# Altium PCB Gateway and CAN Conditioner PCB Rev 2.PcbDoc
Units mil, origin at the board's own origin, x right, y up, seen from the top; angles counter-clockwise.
Board outline 4000 x 3250 mil, 2 copper layers (Top Layer, Bottom Layer); 40 components, 47 nets, 193 pads, 19 vias.
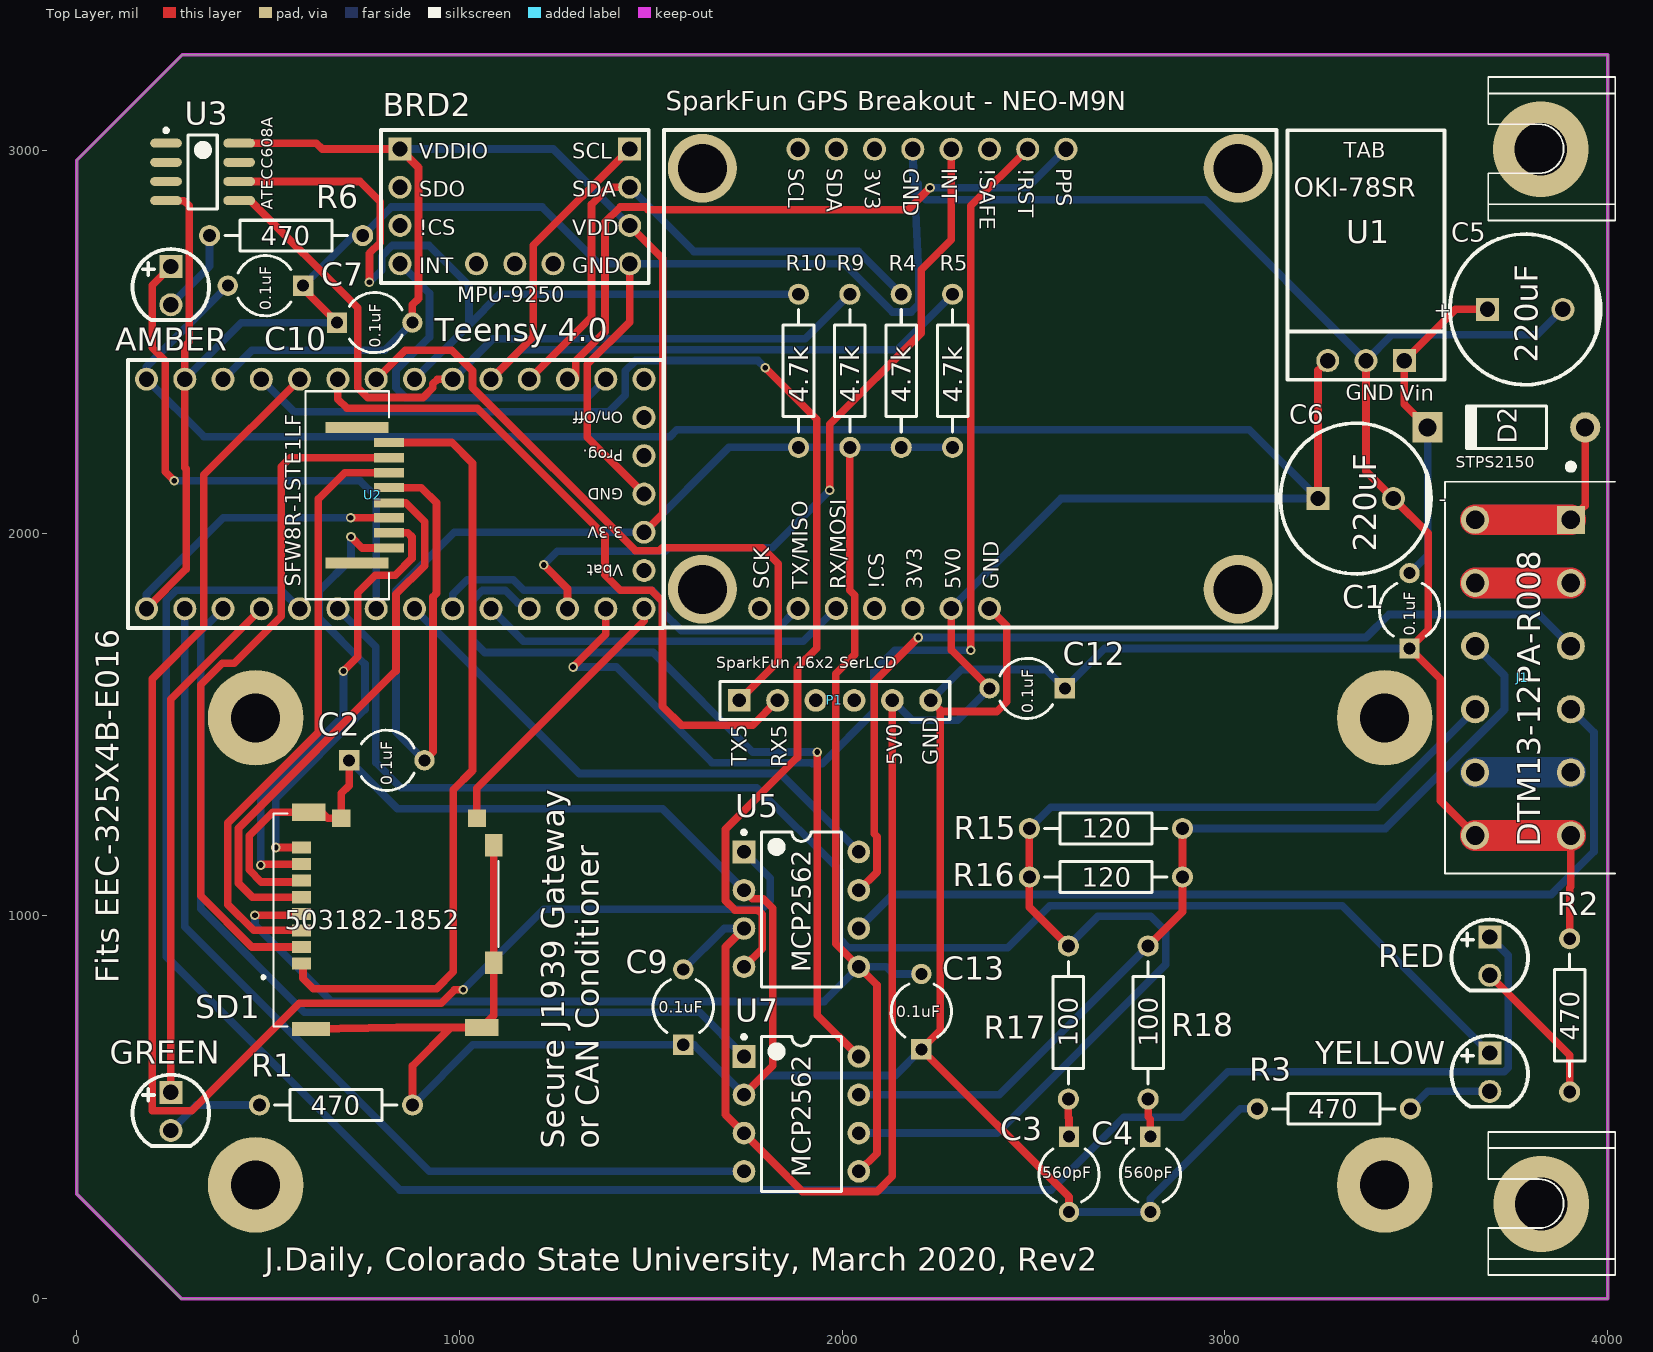
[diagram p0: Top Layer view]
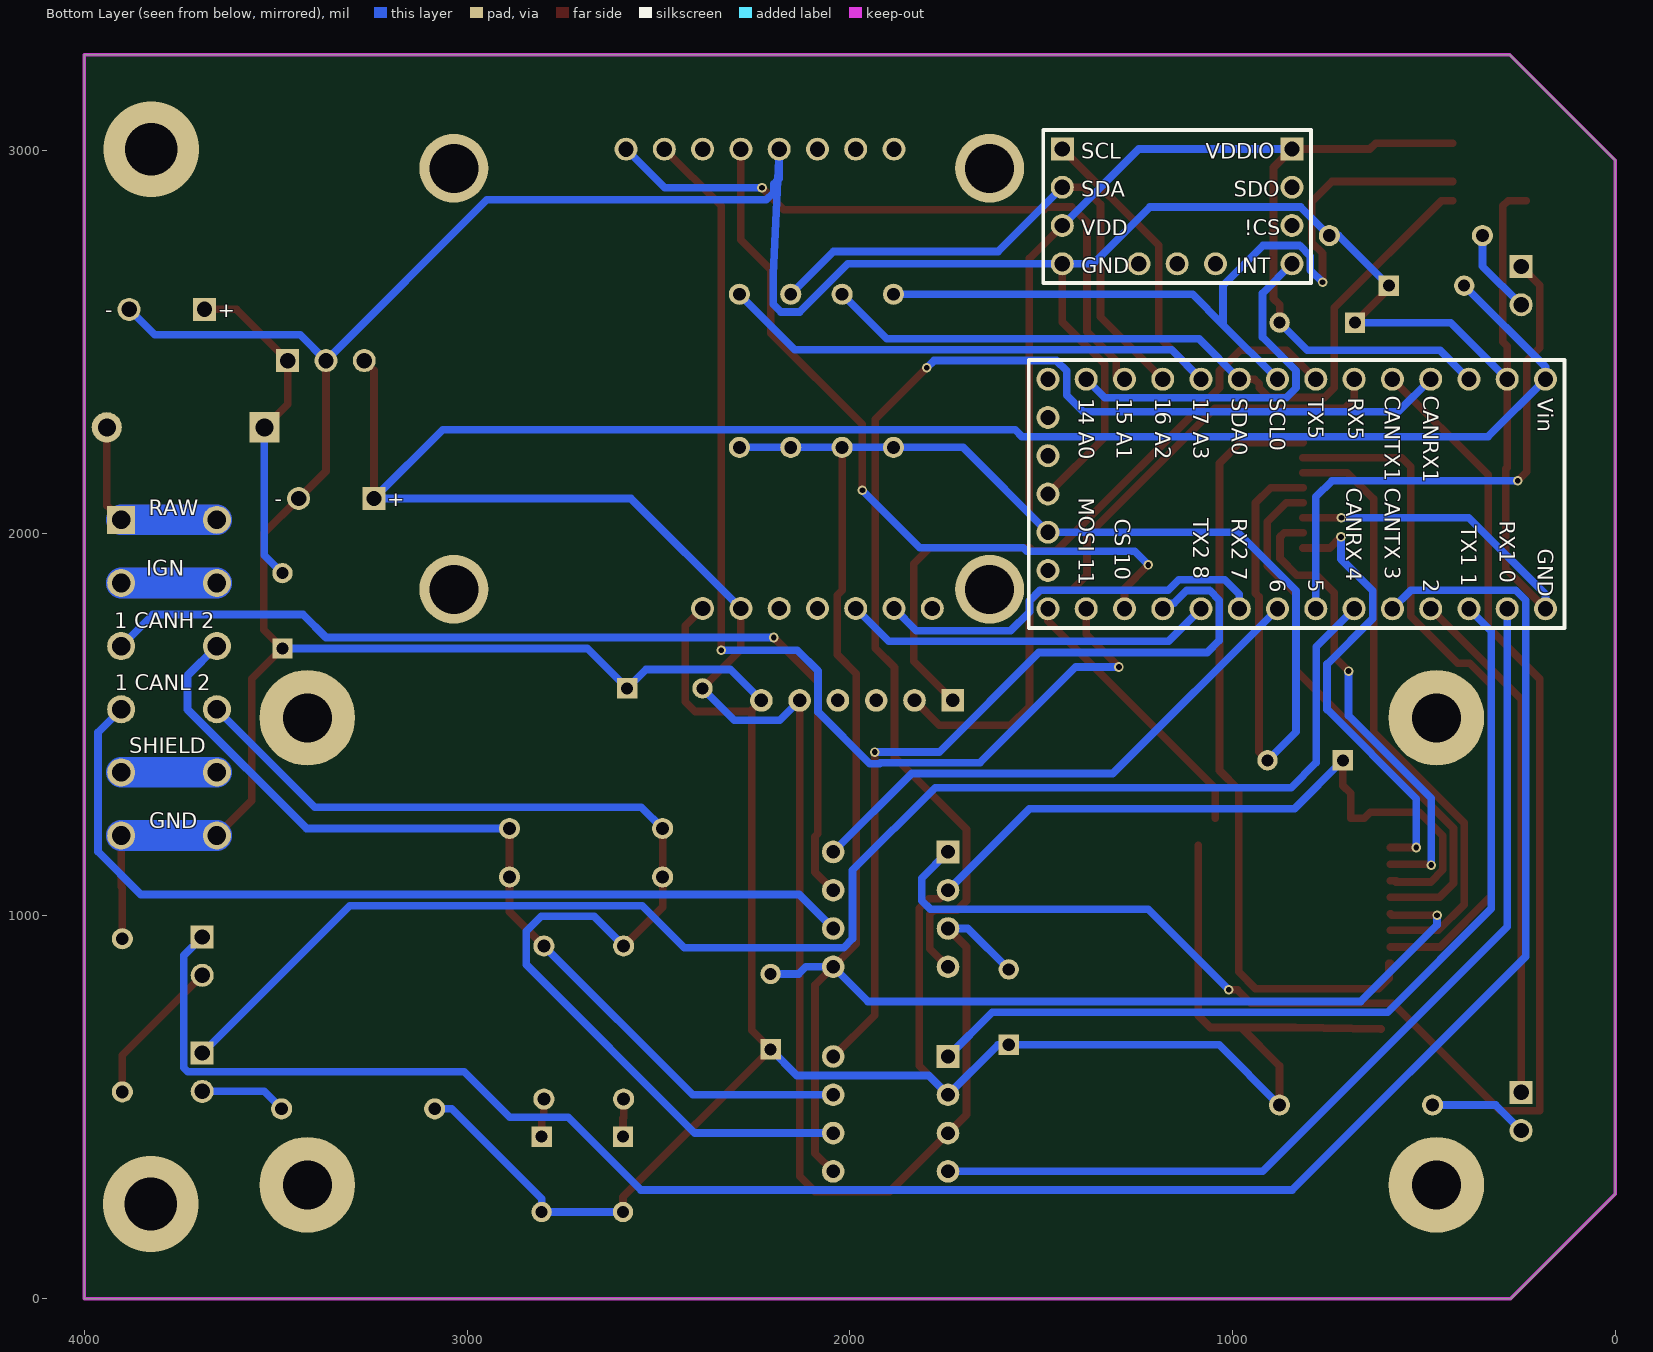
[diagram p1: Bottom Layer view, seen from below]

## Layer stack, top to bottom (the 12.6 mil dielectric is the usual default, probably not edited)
Top Solder: solder mask 0.4, Solder Resist, Dk 3.5
Top Layer: signal copper 1.4
Dielectric 1: dielectric 12.6, FR-4, Dk 4.8
Bottom Layer: signal copper 1.4
Bottom Solder: solder mask 0.4, Solder Resist, Dk 3.5

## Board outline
0,273.11 273.11,0 4000,0 4000,3250 275.59,3250 0,2974.41

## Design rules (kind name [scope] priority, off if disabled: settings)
Clearance [All] p1: gap=8 ignorepadtopadclearanceinfootprint=FALSE
PolygonConnect [All] p1: connectstyle=Relief reliefconductorwidth=10 reliefentries=4 polygonreliefangle="90 Angle" airgapwidth=10
RoutingVias [All] p1: holewidth=15 width=25 viastyle="Through Hole" minholewidth=10 minwidth=20 maxholewidth=30 maxwidth=50
SolderMaskExpansion [All] p1: expansion=4
Width [All] p1: maxlimit=39.37 minlimit=10 preferedwidth=20
30 further rules are at their usual default settings.

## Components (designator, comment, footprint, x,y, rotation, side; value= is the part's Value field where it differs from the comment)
AMBER "Amber" "5mm Rad LED" 247.05,2644.68 r0 top (schematic designator D5)
BRD2 "Sparkfun MPU-9250" "MPU9250 Breakout" 844.68,2703.74 r0 top
C1 "0.1uF" CAPR5-4X5 3482.28,1797.24 r90 top
C2 "0.1uF" CAPR5-4X5 810.04,1406.5 r0 top
C3 "560pF" CAPR5-4X5 2592.52,324.8 r270 top
C4 "560pF" CAPR5-4X5 2805.12,324.8 r270 top
C5 "220uF" "Elec. Cap 5 x 10mm" 3686.02,2584.65 r0 top
C6 "220uF" "Elec. Cap 5 x 10mm" 3243.11,2090.55 r0 top
C7 "0.1uF" CAPR5-4X5 493.11,2646.65 r180 top
C9 "0.1uF" CAPR5-4X5 1584.65,761.81 r90 top
C10 "0.1uF" CAPR5-4X5 778.54,2550.2 r0 top
C12 "0.1uF" CAPR5-4X5 2483.27,1594.49 r180 top
C13 "0.1uF" CAPR5-4X5 2206.69,750 r90 top
D2 "STPS2150" DO-204AL 3735.24,2276.57 r180 top
GREEN "Green" "5mm Rad LED" 247.05,487.2 r0 top (schematic designator D1)
J1 "DTM13-12PA-R008" TE_DTM13-12PA-R008 3826.38,1622.44 r90 top locked
P1 "Header 6" HDR1X6 1730.91,1562.99 r0 top
R1 "470" AXIAL-0.4 677.36,505.91 r0 top
R2 "470" AXIAL-0.4 3900.59,740.35 r90 top
R3 "470" AXIAL-0.4 3284.45,496.06 r180 top
R4 "4.7k" AXIAL-0.4 2154.2,2424.21 r90 top
R5 "4.7k" AXIAL-0.4 2288.39,2424.21 r90 top
R6 "470" AXIAL-0.4 547.05,2777.56 r0 top
R9 "4.7k" AXIAL-0.4 2020.01,2424.21 r90 top
R10 "4.7k" AXIAL-0.4 1885.83,2424.21 r90 top
R15 "120" AXIAL-0.4 2688.98,1228.35 r0 top
R16 "120" AXIAL-0.4 2688.98,1101.71 r0 top
R17 "100" AXIAL-0.4 2590.88,721.46 r90 top
R18 "100" AXIAL-0.4 2799.21,721.46 r90 top
RED "Red" "5mm Rad LED" 3692.91,892.72 r0 top (schematic designator D3)
SD1 "503182-1852" MOLEX_503182-1852 837.6,989.76 r90 top
"SparkFun 16x2 SerLCD" "Comment" LCD14072 467.32,297.24 r0 top locked
"SparkFun GPS Breakout - NEO-M9N" "GPS NEO M9N" "GPS NEO M9N" 3034.45,2953.35 r180 top locked (schematic designator BRD1)
"Teensy 4.0" "Teensy 4.0" "Teensy 4.0" 1482.28,1802.36 r90 top (schematic designator "Teensy 1")
U1 "OKI-78SR" OKI-78SR 3268.5,2450.79 r0 top
U2 "SFW8R-1STE1LF" FCI_SFW8R-1STE1LF 923.95,2099.1 r90 top
U3 "ATECC608A" SOIC-8 328.74,2943.9 r0 top
U5 "MCP2562" DIP-8 1893.31,1017.13 r0 top
U7 "MCP2562" DIP-8 1893.31,482.68 r0 top
YELLOW "Yellow" "5mm Rad LED" 3692.91,589.57 r0 top (schematic designator D4)

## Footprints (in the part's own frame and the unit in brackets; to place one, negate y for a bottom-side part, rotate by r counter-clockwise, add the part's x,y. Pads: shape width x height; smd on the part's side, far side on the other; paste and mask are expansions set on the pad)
"5mm Rad LED" [mil]
  rect 60x60 hole 40: 1(-1.11,52.05)
  round 60 hole 40: 2(-1.11,-47.95)
  silkscreen extent -101,-88 99,98
AXIAL-0.4 [mm] "Axial Device, Thru-Hole; 2 Leads; 0.4 in Pin Spacing"
  round 1.4 hole 0.85: 1(-5.08,0) 2(5.08,0)
  silkscreen extent -4.06,-1.02 4.06,1.02
CAPR5-4X5 [mm] "Capacitor; 2 Leads"
  rect 1.35x1.35 hole 0.8: 1(-2.5,0)
  round 1.35 hole 0.8: 2(2.5,0)
  silkscreen extent -1.69,-2 1.82,2
DIP-8 [mm] "DIP; 8 Leads; Row Spacing 7.62 mm; Pitch 2.54 mm"
  rect 1.5x1.5 hole 0.9: 1(-3.81,3.81)
  round 1.5 hole 0.9: 2(-3.81,1.27) 3(-3.81,-1.27) 4(-3.81,-3.81) 5(3.81,-3.81) 6(3.81,-1.27) 7(3.81,1.27) 8(3.81,3.81)
  silkscreen extent -3.93,-5.15 2.65,5.23, body extent -3.6,-5.15 3.6,5.15, height 5.08
DO-204AL [mm] "Diode, Axial; Body 5.2 x 2.7 mm (LxDia. max), Lead Dia. 0.86 mm (max)"
  round 2 hole 1.2: 1(-5.23,0)
  rect 2x2 hole 1.2: 2(5.23,0)
  silkscreen extent -2.65,-1.4 2.75,1.4
"Elec. Cap 5 x 10mm" [mil] "2 lead polarized Radial Capacitor with 5 mm lead spacing and 10 mm diameter can"
  rect 60x60 hole 40: 1(0,0)
  round 60 hole 40: 2(196.85,0)
  silkscreen extent -98,-197 295,197
FCI_SFW8R-1STE1LF [mil]
  rect 24x79 smd: 1(138,108) 2(98,108) 3(59,108) 4(20,108) 5(-20,108) 6(-59,108) 7(-98,108) 8(-138,108)
  rect 28x165 smd: 9(-177,192) 10(177,192)
  silkscreen extent -272,108 272,326
"GPS NEO M9N" [mil] "Sparkfun Breakout"
  round 180 hole 128: 0(0,1100) 0(0,0) 0(1400,1100) 0(1400,0)
  round 60 hole 40: 1(450,-50) 2(550,-50) 3(650,-50) 4(750,-50) 5(850,-50) 6(950,-50) 7(1050,-50) 8(1150,-50) 9(1250,1150) 10(1150,1150) 11(1050,1150) 12(950,1150) 13(850,1150) 14(750,1150) 15(650,1150)
  silkscreen extent -100,-100 1500,1200
HDR1X6 [mm] "Connector; Header; 6 Position"
  rect 1.5x1.5 hole 0.9: 1(0,0)
  round 1.5 hole 0.9: 2(2.54,0) 3(5.08,0) 4(7.62,0) 5(10.16,0) 6(12.7,0)
  silkscreen extent -1.27,-1.27 13.97,1.27
LCD14072 [mil] "SparkFun 16x2 SerLCD dimensions front"
  round 250 hole 128: 0(0,0) 0(0,1220.47) 0(2950,0) 0(2950,1220.47)
MOLEX_503182-1852 [mm]
  rect 0.8x1.24 smd: 1(-2.9,6.355) 2(-1.8,6.355) 3(-0.7,6.355) 4(0.4,6.355) 5(1.5,6.355) 6(2.6,6.355) 7(3.7,6.355) 8(4.8,6.355)
  rect 1.16x1.2 smd: DT(6.74,-5.275)
  rect 0.95x2.5 smd: P1(-7.245,5.725)
  rect 1.15x2.2 smd: P2(7.145,5.875) P3(-7.145,-5.605)
  rect 1.5x1.15 smd: P4(-2.84,-6.4) P5(4.94,-6.4)
  rect 1.16x1.25 smd: SW(6.74,3.725)
  silkscreen extent -7.07,-6.72 7.07,8.99
"MPU9250 Breakout" [mil] "SparkFun IMU Breakout - MPU-9250"
  rect 60x60 hole 40: 1(0,300) 8(600,300)
  round 60 hole 40: 2(0,200) 3(0,100) 4(0,0) 5(600,0) 6(600,100) 7(600,200) 9(200,0) 10(300,0) 11(400,0)
  silkscreen extent -50,-50 650,350
OKI-78SR [mil] "Horizontal Mount SIP DC/DC Converter"
  rect 60x60 hole 40: 1(200,0)
  round 60 hole 40: 2(100,0) 3(0,0)
  silkscreen extent -105,-50 305,602
SOIC-8 [mm]
  oval 2.1x0.6 smd: 1(-2.425,1.905) 2(-2.425,0.635) 3(-2.425,-0.635) 4(-2.425,-1.905) 5(2.425,-1.905) 6(2.425,-0.635) 7(2.425,0.635) 8(2.425,1.905)
  silkscreen extent -2.55,-2.45 0.97,2.88
TE_DTM13-12PA-R008 [mm]
  rect 1.86x1.86 hole 1.24: 1(10.475,-1.96)
  round 1.86 hole 1.24: 2(6.285,-1.96) 3(2.095,-1.96) 4(-2.095,-1.96) 5(-6.285,-1.96) 6(-10.475,-1.96) 7(-10.475,4.39) 8(-6.285,4.39) 9(-2.095,4.39) 10(2.095,4.39) 11(6.285,4.39) 12(10.475,4.39)
  silkscreen extent -39.65,-4.91 39.85,6.39
"Teensy 4.0" [mil] "32 bit Arduino Compatible Microcontroller www.pjrc.com/teensy"
  round 60 hole 40: 0(0,1200) 1(0,1100) 2(0,1000) 3(0,900) 3V3a(600,1100) 3V3b(200,0) 4(0,800) 5(0,700) 6(0,600) 7(0,500) 8(0,400) 9(0,300) 10(0,200) 11(0,100) 12(0,0) 13(600,0) 14(600,100) 15(600,200) 16(600,300) 17(600,400) 18(600,500) 19(600,600) 20(600,700) 21(600,800) 22(600,900) 23(600,1000) G1(0,1300) G2(600,1200) G3(300,0) On(500,0) P(400,0) VBat(100,0) Vin(600,1300)
  silkscreen extent -50,-50 650,1348

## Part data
AMBER: library part "LED - SMD", "Amber 588nm LED Indication - Discrete 2.1V Radial", Manufacturer="Lite-On Inc.", PartNumber=LTL-4273, Supplier Part Number 1=160-1966-ND
BRD2: library part "MPU-9350 Breakout"
C1 C2 C7 C9 C10 C12 C13: library part Cap, "0.1µF ±10% 50V Ceramic Capacitor X7R Radial", Manufacturer="TDK Corporation", PartNumber=FA28X7R1H104KNU00, Supplier Part Number 1=445-175529-ND
C3 C4: library part Cap, "560pF ±5% 100V Ceramic Capacitor C0G, NP0 Radial", Manufacturer="TDK Corporation", PartNumber=FA28C0G2A561JNU00, Supplier Part Number 1=445-175528-ND
C5 C6: library part "Electrolytic Cap", "220µF 50V Aluminum Electrolytic Capacitors Radial, Can 175 mOhm @ 10kHz 5000 Hrs @ 105°C", Manufacturer="EPCOS (TDK)", PartNumber=B41858C6227M000, Supplier Part Number 1=495-6000-ND
D2: library part "Diode 1N4003", "Diode Schottky 150V 2A Through Hole DO-15", Manufacturer=STMicroelectronics, Supplier Part Number 1=497-3213-1-ND
GREEN: library part "LED - SMD", "Green 569nm LED Indication - Discrete 2.1V Radial", Manufacturer="Lite-On Inc.", PartNumber=LTL-4233, Supplier Part Number 1=160-1130-ND
J1: "DTM Series, 4.19mm Pitch 12 Way 2 Row Right Angle PCB Header, Solder Termination", Package=None
P1: "Header, 6-Pin"
R1 R2 R3 R6: library part "Chip Resistor", "330 Ohms ±1% 0.1W, 1/10W Chip Resistor 0603 (1608 Metric) Automotive AEC-Q200, High Voltage Thick Film", Manufacturer="Stackpole Electronics Inc", PartNumber=CF14JT470R, Supplier Part Number 1=CF14JT470RCT-ND
R4 R5 R9 R10: library part "Chip Resistor", "4.7 kOhms ±5% 0.25W, 1/4W Through Hole Resistor Axial Flame Retardant Coating, Safety Carbon Film", Manufacturer="Stackpole Electronics Inc", PartNumber=CF14JT4K70, Supplier Part Number 1=CF14JT4K70CT-ND
R15 R16: library part "Chip Resistor", "120 Ohms ±5% 0.25W, 1/4W Through Hole Resistor Axial Flame Retardant Coating, Safety Carbon Film", Manufacturer="Stackpole Electronics Inc", PartNumber=CF14JT120RCT-ND
R17 R18: library part "Chip Resistor", "100 Ohms ±5% 0.25W, 1/4W Through Hole Resistor Axial Flame Retardant Coating, Safety Carbon Film", Manufacturer="Stackpole Electronics Inc", PartNumber=CF14JT100R, Supplier Part Number 1=CF14JT100RCT-ND
RED: library part "LED - SMD", "Red 623nm LED Indication - Discrete 2V Radial", Manufacturer="Lite-On Inc.", PartNumber=LTL-4223, Supplier Part Number 1=160-1127-ND
SD1: "MICRO SD NORMAL ULTRALOWPRO8CKTE", Manufacturer=Molex, PartNumber=5031821852, Supplier Part Number 1=WM12834CT-ND
"Teensy 4.0": library part Teensy_4.0, "32 Bit Arduino-Compatible iMX Microcontroller", Manufacturer=PRJC, Supplier Part Number 1=1568-DEV-15583-ND
U1: library part 7805, "5V DC/DC Converter (7805 replacement)", Manufacturer="Murata Power Solutions Inc.", PartNumber=OKI-78SR-5/1.5-W36H-C, Supplier Part Number 1=811-2692-ND
U2: "8 Position FFC, FPC Connector Contacts, Bottom 0.039 _1.00mm_ Surface Mount, Right Angle", Package=None
U3: library part ATECC508A, "Authentication Chip IC Networking and Communications 8-SOIC", Manufacturer="Microchip Technology", PartNumber=ATECC608A-SSHDA-T, Supplier Part Number 1=ATECC608A-SSHDA-TCT-ND
U5 U7: library part MCP2558FD, "Microchip CAN FD Transceiver with Silent Mode", Manufacturer=Microchip, PartNumber=MCP2562-E/P, Supplier Part Number 1=MCP2562-E/P-ND
YELLOW: library part "LED - SMD", "Yellow 588nm LED Indication - Discrete 2.1V Radial", Manufacturer="Lite-On Inc.", PartNumber=LTL-4253, Supplier Part Number 1=160-1133-ND

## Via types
v1: diameter 25, hole 15, Top Layer to Bottom Layer, 17 vias
v2: diameter 250, hole 137.8, Top Layer to Bottom Layer, 2 vias

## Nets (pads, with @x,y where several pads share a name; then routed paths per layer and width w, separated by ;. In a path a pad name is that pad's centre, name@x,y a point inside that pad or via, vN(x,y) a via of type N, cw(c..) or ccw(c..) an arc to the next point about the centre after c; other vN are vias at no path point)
3V3: "Teensy 4.0.3V3a" "Teensy 4.0.3V3b" BRD2.1 BRD2.6 C2.2 C10.2 C13.2 R4.1 R5.1 R9.1 R10.1 SD1.4 U2.4 U3.8 U5.5 U7.5 | length 9913.2
  Top Layer w20: U3.8 626,3018.9 641.16,3003.74 BRD2.1 893,2955.43 893,2613 876.97,2596.97 C10.2 ; v1(465.55,1001.97) 583.86,1001.97 SD1.4 ; U2.4 900,2119.09 940,2079.09 940,1843 931,1834 931,1429.03 C2.2 ; BRD2.6 1531,2717.43 1531,2051.08 1482.28,2002.36 ; R9.1 2020.01,1851 2033,1838.01 2033,1683 1983,1633 1983,927.43 U5.5 2091,819.43 2091,380.37 U7.5
  Bottom Layer w20: 382.28,2402.36 457.92,2478 804.77,2478 C10.2 ; v1(465.55,1001.97) 465.55,976.4 665.37,776.59 1952.77,776.59 U5.5 2115,867.13 2133.7,848.42 C13.2 ; BRD2.1 1244.69,3003.74 BRD2.6 ; C2.2 834,1480.96 834,1850 986.36,2002.36 1482.28,2002.36 1704.14,2224.21 R10.1 R9.1 R4.1 R5.1
5V0: "SparkFun GPS Breakout - NEO-M9N.14" "Teensy 4.0.Vin" C6.1 C7.2 C9.2 C12.2 P1.5 U1.3 U5.3 U7.3 | length 8033.9
  Top Layer w20: U5.3 1695,918.82 1695,480.99 U7.3 1895.99,280 2091,280 2130.91,319.91 P1.5 ; 2284.45,1803.35 2284.45,1694.88 C12.2 ; C6.1 3243.11,2425.39 U1.3
  Bottom Layer w20: C7.2 182.28,2434.25 182.28,2402.36 332.65,2252 1550,2252 1568,2270 3063.66,2270 C6.1 2571.65,2090.55 2284.45,1803.35 ; C9.2 1691.54,967.13 U5.3 ; P1.5 2182.9,1511 2301.35,1511 C12.2
12V0: C1.2 C5.1 D2.2 U1.1 | length 872.8
  Top Layer w20: D2.2 3468.5,2337.4 U1.1 3602.36,2584.65 C5.1
  Bottom Layer w20: C1.2 3529.33,1942.72 D2.2
CAN1H: J1.3 U5.7 | length 2494.7
  Top Layer w20: U5.7 2091,1114.82 2091,1207 2083.38,1214.62 2083.38,1611.92 v1(2198.82,1727.36)
  Bottom Layer w20: v1(2198.82,1727.36) 3368.36,1727.36 3428.4,1787.4 3821.06,1787.4 J1.3
CAN1L: J1.4 U5.6 | length 2400.9
  Bottom Layer w20: U5.6 2132.18,1056 3852,1056 3964,1168 3964,1479.5 J1.4
CAN1RX: "Teensy 4.0.23" U5.4 | length 3266.4
  Top Layer w20: U5.4 1790.84,914.65 1790.84,1004.16 1780,1015 1720,1015 1695,1040 1695,1226 1883,1414 1883,1649 1933,1699 1933,2298 v1(1799,2432)
  Bottom Layer w20: 482.28,2402.36 567.65,2317 1390,2317 1433,2360 1433,2424 1460,2451 1780,2451 v1(1799,2432)
CAN1TX: "Teensy 4.0.22" U5.1 | length 4068.9
  Top Layer w20: 582.28,2402.36 332,2152.08 332,1754 197,1619 197,491 300,491 581,772 952,772 987.09,807.09 v1(1009.84,807.09)
  Bottom Layer w20: v1(1009.84,807.09) 1219.76,1017 1789,1017 1812,1040 1812,1098.43 U5.1
CAN2H: J1.10 R15.2 R16.2 R18.2 U7.7 | length 2428.5
  Top Layer w20: R18.2 2888.98,1011.22 R16.2 R15.2
  Bottom Layer w20: U7.7 2410.43,532.68 R18.2 ; R15.2 3419.29,1228.35 3730.31,1539.37 3730.31,1628.15 J1.10
CAN2L: J1.9 R15.1 R16.1 R17.2 U7.6 | length 3016
  Top Layer w20: R15.1 R16.1 2488.98,1023.36 R17.2
  Bottom Layer w20: U7.6 2404.68,432.68 2845,873 2845,960 2806.24,998.76 2668.18,998.76 R17.2 ; R15.1 2544.63,1284 3397.58,1284 J1.9
CAN2RX: "Teensy 4.0.0" U7.4 | length 2556.4
  Bottom Layer w20: 282.28,1802.36 282.28,971.72 921.32,332.68 U7.4
CAN2TX: "Teensy 4.0.1" U7.1 | length 2386.6
  Bottom Layer w20: 382.28,1802.36 324,1744.08 324,1019.37 594.79,748.59 1627.4,748.59 U7.1
DAT0: SD1.7 U2.7 | length 1223.2
  Top Layer w20: v1(481.11,1132.87) 483.67,1135.43 SD1.7 ; v1(696.85,1639.76) 734,1676.91 734,1844 780,1890 832,1890 876,1934 876,1990 864.91,2001.09 U2.7
  Bottom Layer w20: v1(481.11,1132.87) 481.11,1307.11 696.85,1522.85 v1(696.85,1639.76)
DAT1: SD1.8 U2.8 | length 1170.3
  Top Layer w20: v1(520,1178.74) SD1.8 ; v1(716.54,1990.16) 745.6,1961.09 U2.8
  Bottom Layer w20: v1(520,1178.74) 520,1306.4 753,1539.4 753,1658 634,1777 634,1850 716.54,1932.54 v1(716.54,1990.16)
DAT2: SD1.1 U2.1 | length 2054.8
  Top Layer w20: SD1.1 591,875.59 591,837 618,810 940,810 984,854 984,1330 1034,1380 1034,2183.09 980,2237.09 U2.1
DAT3: SD1.2 U2.2 | length 1836.5
  Top Layer w20: SD1.2 552.18,918.9 551.94,918.65 457.84,918.65 324,1052.49 324,1604 380,1660 411,1660 534,1783 534,2173 558.09,2197.09 U2.2
GND: "SparkFun GPS Breakout - NEO-M9N.5" "SparkFun GPS Breakout - NEO-M9N.15" "Teensy 4.0.G1" "Teensy 4.0.G2" "Teensy 4.0.G3" BRD2.5 C1.1 C2.1 C3.2 C4.2 C5.2 C6.2 C7.1 C9.1 C10.1 C12.1 C13.1 J1.6 J1.7 P1.6 R1.2 R2.2 R3.2 R6.2 SD1.6 SD1.P1 SD1.P2 SD1.P3 SD1.P4 SD1.P5 SD1.SW U1.2 U2.6 U3.4 U5.2 U7.2 | length 18492.1
  Top Layer w20: 182.28,1802.36 286.48,1906.56 286.48,2167.54 282.28,2171.74 282.28,2402.36 282.28,2488.28 294,2500 294,2854.9 280,2868.9 U3.4 ; SD1.6 572.99,1092.12 572.99,1088.5 482.35,1088.5 450.61,1120.24 450.61,1209.06 512.62,1271.06 SD1.P2 640,1271.06 655.95,1255.12 SD1.SW 690.94,1320 711.61,1340.67 C2.1 ; C7.1 591.54,2638.78 C10.1 ; SD1.P1 836.94,708.46 977.46,708.46 ; v1(715.55,2040.35) 815.68,2040.35 U2.6 ; R1.2 877.36,608.36 977.46,708.46 ; SD1.P5 SD1.P4 1089.57,739.76 SD1.P3 977.46,708.46 ; BRD2.5 1444.69,2551.69 1334,2441 1334,2250.65 1482.28,2102.36 ; U7.2 1818.84,608.21 1818.84,1020 1793.71,1045.13 1765.31,1045.13 U5.2 ; P1.6 2256,1537.9 ; 2384.45,1803.35 2430,1757.79 2430,1560 2404,1534 2259.9,1534 2256,1537.9 ; C3.2 2592.52,265.75 C13.1 2256,700.88 2256,1537.9 ; U1.2 3368.5,2162.01 C6.2 3531,1999.51 3531,1747.53 C1.1 3562,1619.1 3562,1301.58 J1.7 ; R2.2 3900.59,1073 3903.54,1075.95 J1.6
  Top Layer w80: J1.7 J1.6
  Bottom Layer w20: 182.28,1802.36 182.28,1840 382.64,2040.35 v1(715.55,2040.35) ; 282.28,2402.36 430.12,2550.2 C10.1 ; C7.1 722.44,2777.56 R6.2 821.49,2852 1216,2852 1364.26,2703.74 BRD2.5 2005.26,2703.74 2131,2578 2180,2578 2200,2598 2200,2676 2188.28,2922.67 ; C2.1 838.11,1280 1530.43,1280 U5.2 ; R1.2 1034.84,663.39 C9.1 1612.6,663.39 U7.2 1793.63,583 2138.12,583 C13.1 ; P1.6 2311.91,1644 2532.18,1644 C12.1 2686.02,1698.82 C1.1 ; C3.2 C4.2 2805.12,261.18 3040,496.06 R3.2 ; C5.2 3816.23,2518 3435.72,2518 U1.2 2948.34,2870.95 2217.81,2870.95 2198.83,2889.93 2198.83,2912.12 2188.28,2922.67 ; 2188.28,2922.67 2184.45,3003.35 2184.45,2926.5 2188.28,2922.67
GPS_INT: "SparkFun GPS Breakout - NEO-M9N.4" "Teensy 4.0.10" | length 1991
  Top Layer w20: v1(1220,1917) 1282.28,1854.72 1282.28,1802.36 ; v1(1967,2112) 1967,2284 2206,2523 2206,2688 2284.45,2766.45 2284.45,3003.35
  Bottom Layer w20: v1(1220,1917) 1256,1953 1538,1953 1547,1962 1817,1962 v1(1967,2112)
GPS_RESET: "SparkFun GPS Breakout - NEO-M9N.2" "Teensy 4.0.11" | length 2887.6
  Top Layer w20: v1(1296.72,1650.43) 1382.28,1736 1382.28,1802.36 ; v1(2336,1694) 2336,2854.9 2484.45,3003.35
  Bottom Layer w20: v1(1296.72,1650.43) 1409.57,1650.43 1659.85,1400.15 1919.91,1400.15 1922.41,1397.65 1947.67,1397.65 2083,1532.98 2083,1640 2137,1694 v1(2336,1694)
GPS_RX: "SparkFun GPS Breakout - NEO-M9N.11" "Teensy 4.0.8" | length 973
  Bottom Layer w20: 1082.28,1802.36 1167.3,1717.35 1898.45,1717.35 1984.45,1803.35
GPS_TX: "SparkFun GPS Breakout - NEO-M9N.10" "Teensy 4.0.7" | length 1052
  Bottom Layer w20: 982.28,1802.36 982.28,1840.65 1020,1878.36 1140.46,1878.36 1167.82,1851 1503,1851 1530.28,1823.72 1530.28,1795.06 1580,1745.35 1826.45,1745.35 1884.45,1803.35
Ignition: J1.2 J1.11 | length 500
  Top Layer w80: J1.11 J1.2
  Bottom Layer w80: J1.11 J1.2
INT: "Teensy 4.0.14" BRD2.4 | length 970.9
  Bottom Layer w20: BRD2.4 921.54,2626.88 921.54,2511.54 834,2424 834,2380 860,2354 1333.92,2354 1382.28,2402.36
LED1: "Teensy 4.0.2" GREEN.1 | length 1361
  Top Layer w20: GREEN.1 245.94,1566.01 482.28,1802.36
LED2: "Teensy 4.0.3" RED.1 | length 5562.7
  Bottom Layer w20: 582.28,1802.36 533.65,1851 260,1851 234,1825 234,894 844,284 2546,284 2736,474 2888,474 3007,593 3730,593 3740,603 3740,896.58 RED.1
LED3: "Teensy 4.0.4" YELLOW.1 | length 3863.6
  Bottom Layer w20: 682.28,1802.36 781,1703.65 781,1401 847,1335 1777,1335 1993,1119 1993,940 2016,917 2432,917 2542,1027 3306.43,1027 YELLOW.1
LED4: "Teensy 4.0.5" AMBER.1 | length 1441.2
  Top Layer w20: AMBER.1 197,2647.8 197,2484 231,2450 231,2161 v1(255,2137)
  Bottom Layer w20: v1(255,2137) 740,2137 782.28,2094.72 782.28,1802.36
NetC3_1: C3.1 R17.1 | length 98.9
  Top Layer w20: R17.1 2590.88,472.64 2592.52,471 C3.1
NetC4_1: C4.1 R18.1 | length 100.7
  Top Layer w20: R18.1 2799.21,474.91 2805.12,469 C4.1
NetD1_2: GREEN.2 R1.1 | length 259
  Bottom Layer w20: GREEN.2 312.58,505.91 R1.1
NetD3_2: R2.1 RED.2 | length 390.9
  Top Layer w20: RED.2 3900.59,635.99 R2.1
NetD4_2: R3.1 YELLOW.2 | length 226.2
  Bottom Layer w20: R3.1 3530.01,541.62 YELLOW.2
NetD5_2: AMBER.2 R6.1 | length 222.7
  Bottom Layer w20: AMBER.2 347.05,2697.85 R6.1
PPS: "SparkFun GPS Breakout - NEO-M9N.1" "Teensy 4.0.15" | length 1751.7
  Top Layer w20: 1282.28,2402.36 1303.4,2402.36 1303.4,2450 1380,2526.6 1380,2812 1420,2852 1486,2852 1492.65,2845.35 2172.12,2845.35 v1(2229.33,2902.56)
  Bottom Layer w20: v1(2229.33,2902.56) 2483.66,2902.56 2584.45,3003.35
RAW: D2.1 J1.1 J1.12 | length 757.3
  Top Layer w20: J1.1 3941.14,2072.44 D2.1
  Top Layer w80: J1.12 J1.1
  Bottom Layer w80: J1.12 J1.1
RX5: "Teensy 4.0.21" P1.2 | length 1801.2
  Top Layer w20: 682.28,2402.36 682.28,2350.36 706.28,2326.36 1046.64,2326.36 1380,1993 1380,1891 1420,1851 1501.53,1851 1530.28,1822.25 1530.28,1547.72 1580,1498 1765.91,1498 P1.2
SCK: "Teensy 4.0.13"
SCL: "Teensy 4.0.19" R10.2 U3.6 | length 2174.5
  Top Layer w20: U3.6 740,2918.9 792.61,2866.29 792.61,2758.69 764.76,2730.85 v1(764.76,2655.51)
  Bottom Layer w20: v1(764.76,2655.51) 796.69,2687.43 796.69,2723.62 824.8,2751.74 920.26,2751.74 1025,2647 1025,2545.08 ; 882.28,2402.36 1025,2545.08 ; R10.2 1104.14,2624.21 1025,2545.08
SCL1: "Teensy 4.0.17" BRD2.8 R5.2 | length 2049.5
  Top Layer w20: 1082.28,2402.36 1193,2513.08 1193,2752.05 BRD2.8
  Bottom Layer w20: 1082.28,2402.36 1158.92,2479 2143.17,2479 R5.2
"SD Contact": "Teensy 4.0.12" SD1.DT | length 728.3
  Top Layer w20: SD1.DT 1045.28,1334 1482.28,1771.01 1482.28,1802.36
SD_CLK: SD1.5 U2.5 | length 1439.6
  Top Layer w20: SD1.5 459.17,1048.82 422.61,1085.37 422.61,1228.62 834,1640 834,1840 909.1,1915.1 909.1,2029.99 860,2079.09 U2.5
SD_CMD: SD1.3 U2.3 | length 1591.5
  Top Layer w20: SD1.3 462.18,962.2 394.61,1029.77 394.61,1242.77 631,1479.16 631,2089.09 700,2158.09 U2.3
SDA: "Teensy 4.0.18" R9.2 U3.5 | length 2048.8
  Top Layer w20: U3.5 454,2868.9 734.28,2588.61 734.28,2380 759.92,2354.36 904.65,2354.36 930.28,2380 930.28,2390 942.65,2402.36 982.28,2402.36
  Bottom Layer w20: 982.28,2402.36 1087.55,2507.63 1903.43,2507.63 R9.2
SDA1: "Teensy 4.0.16" BRD2.7 R4.2 | length 1468
  Top Layer w20: 1182.28,2402.36 1345,2565.08 1345,2859.77 1388.97,2903.74 BRD2.7
  Bottom Layer w20: BRD2.7 1612.43,2736 2042.41,2736 R4.2
SHIELD: J1.5 J1.8 | length 250
  Bottom Layer w80: J1.8 J1.5
"Silent 1": "Teensy 4.0.6" U5.8 | length 1424.1
  Bottom Layer w20: 882.28,1802.36 1312.5,1372.15 1838.28,1372.15 U5.8
"Silent 2": "Teensy 4.0.9" U7.8 | length 2153.9
  Top Layer w20: v1(1935.04,1428.15) 1935.04,740.95 U7.8
  Bottom Layer w20: 1182.28,1802.36 1182.28,1817 1153,1817 1119.64,1850.36 1060,1850.36 1034.28,1824.65 1034.28,1719.72 1065.82,1688.18 1505.82,1688.18 1765.85,1428.15 v1(1935.04,1428.15)
TX5: "Teensy 4.0.20" P1.1 | length 1744.9
  Top Layer w20: 782.28,2402.36 857.92,2478 980,2478 1034,2424 1034,2380 1460,1954 1522,1954 1530,1962 1791,1962 1833,1920 1833,1665.09 P1.1
pads on no net: "SparkFun 16x2 SerLCD.0" "SparkFun GPS Breakout - NEO-M9N.0" "SparkFun GPS Breakout - NEO-M9N.3" "SparkFun GPS Breakout - NEO-M9N.6" "SparkFun GPS Breakout - NEO-M9N.7" "SparkFun GPS Breakout - NEO-M9N.8" "SparkFun GPS Breakout - NEO-M9N.9" "SparkFun GPS Breakout - NEO-M9N.12" "SparkFun GPS Breakout - NEO-M9N.13" "Teensy 4.0.On" "Teensy 4.0.P" "Teensy 4.0.VBat" BRD2.2 BRD2.3 BRD2.9 BRD2.10 BRD2.11 P1.3 P1.4 U2.9 U2.10 U3.1 U3.2 U3.3 U3.7
copper on no net: | length 250
  Bottom Layer w80: 3653.54,1210.04 3903.54,1210.04
  other v2: 3826.38,247.24 3824.8,3002.76

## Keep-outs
Keep-Out Layer:
  the board outline again, w10

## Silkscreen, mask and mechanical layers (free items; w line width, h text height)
Top Overlay:
  text "5V0" at 2156.5,1393.7 h40 r90
  text "TX5" at 1750,1392.72 h40 r90
  text "GND" at 2251,1393 h40 r90
  text "RX5" at 1855.32,1388.78 h40 r90
  text "Fits EEC-325X4B-E016" at 110.24,823.82 h60 r90
  text "Secure J1939 Gateway / or CAN Conditioner" at 1364.17,391.73 h60 r90
  text "J.Daily, Colorado State University, March 2020, Rev2" at 491.14,72.83 h60
Bottom Overlay:
  text "RAW" at 3831.69,2047.24 h40
  text "IGN" at 3837.6,1888.78 h40
  text "1 CANH 2" at 3921.26,1750.98 h40
  text "1 CANL 2" at 3920.28,1589.57 h40
  text "SHIELD" at 3881.89,1425.2 h40
  text "GND" at 3829.72,1229.33 h40
Mechanical 1:
  lines w10: 0,1625 4000,1625

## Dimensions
2230.91,1562.99 to 3417.32,1517.72 on Mechanical 1
3903.54,1210.04 to 4000,0 on Mechanical 1
3824.8,3002.76 to 4000,1625 on Mechanical 1
3826.38,247.24 to 4000,0 on Mechanical 1
4000,1625 to 3826.38,247.24 on Mechanical 1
